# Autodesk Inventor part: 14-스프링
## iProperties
Created: 2014-11
Part Number: 14-스프링
Document SubType Name: Modeling
Designer: elite
Density: 7.86 g/cm^3
Material: 강, 연강
Mass: 2.83582 g
Surface Area: 9.77252 cm^2
Volume: 0.360792 cm^3
Author: elite
